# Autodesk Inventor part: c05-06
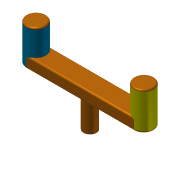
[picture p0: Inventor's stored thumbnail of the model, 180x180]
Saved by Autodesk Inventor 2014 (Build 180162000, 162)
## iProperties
Created: 2010-11
Part Number: c05-06
Material: Generic
Document SubType Name: Modeling
Designer: Thom Tremblay
Density: 1 g/cm^3
Appearance: Orange
Author: Thom Tremblay
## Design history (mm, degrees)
sketch "Sketch1" dims "d4" = 27, "d5" = 6
  geometry: L1 (-16.5, -3)-(16.5, -3); L2 (16.5, -3)-(16.5, 3); L3 (16.5, 3)-(-16.5, 3); L4 (-16.5, 3)-(-16.5, -3); C1 r 1.986 at (0, 0); 4 further points
  constraints: 8 end point, 3 midpoint, 3 vertical alignment, 2 parallel, 1 centre point, 1 coincident, 1 horizontal, 1 horizontal alignment, 1 perpendicular, 4 other
extrude "Extrusion1" new body sketch "Sketch1" distance "d0" = 8; taper "d1" = 0 deg
extrude "Extrusion2" join sketch "Sketch1" distance "d2" = 3.5; taper "d3" = 0 deg
extrude "Extrusion3" join sketch "Sketch1" distance "d6" = 12.75; taper "d7" = 0 deg
fillet "Fillet1" dims "d8" = 0.5
fillet "Fillet2" dims "d9" = 0.5
body "Solid1"
